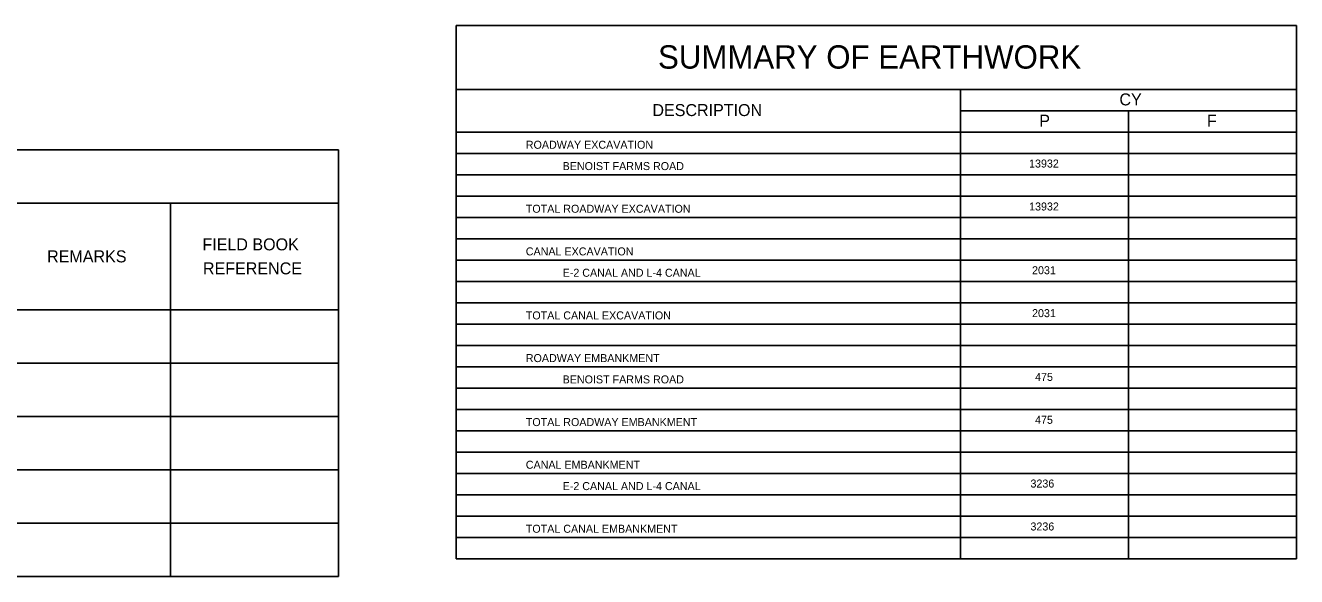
# Model space of a CAD drawing. Extents: x 0.1 to 38.9, y -11.7 to 25.8.
# Drawn here: x 29.62 to 38.87, y 21.71 to 25.72 of the extents above; entities that cross this region are included whole.
import ezdxf

# ---------------------------------------------------------------- set-up
doc = ezdxf.new("R2010")
doc.units = 0
doc.layers.add('Default', color=7, linetype='Continuous')

msp = doc.modelspace()

# ---------------------------------------------------------------- linework, layer by layer
at = {"layer": 'Default'}
for p, q in [((32.7527, 25.724), (32.7527, 21.8424)), ((32.7527, 25.724), (38.8663, 25.724)), ((38.8663, 25.724), (38.8663, 21.8424)), ((32.7527, 25.2582), (38.8663, 25.2582)), ((36.4209, 25.2582), (36.4209, 21.8424)), ((36.4209, 25.103), (38.8663, 25.103)), ((37.6436, 25.103), (37.6436, 21.8424)), ((32.7527, 24.9477), (38.8663, 24.9477)), ((17.4943, 24.8184), (31.8977, 24.8184)), ((31.8977, 24.8184), (31.8977, 21.7126)), ((32.7527, 24.7924), (38.8663, 24.7924)), ((32.7527, 24.6372), (38.8663, 24.6372)), ((17.4943, 24.4302), (31.8977, 24.4302)), ((30.6747, 24.4302), (30.6747, 21.7126)), ((32.7527, 24.4819), (38.8663, 24.4819)), ((32.7527, 24.3266), (38.8663, 24.3266)), ((32.7527, 24.1714), (38.8663, 24.1714)), ((32.7527, 24.0161), (38.8663, 24.0161)), ((32.7527, 23.8608), (38.8663, 23.8608)), ((32.7527, 23.7056), (38.8663, 23.7056)), ((17.4943, 23.6537), (31.8977, 23.6537)), ((32.7527, 23.5503), (38.8663, 23.5503)), ((32.7527, 23.395), (38.8663, 23.395)), ((17.4943, 23.2655), (31.8977, 23.2655)), ((32.7527, 23.2398), (38.8663, 23.2398)), ((32.7527, 23.0845), (38.8663, 23.0845)), ((17.4943, 22.8773), (31.8977, 22.8773)), ((32.7527, 22.9293), (38.8663, 22.9293)), ((32.7527, 22.774), (38.8663, 22.774)), ((32.7527, 22.6187), (38.8663, 22.6187)), ((17.4943, 22.489), (31.8977, 22.489)), ((32.7527, 22.4635), (38.8663, 22.4635)), ((32.7527, 22.3082), (38.8663, 22.3082)), ((17.4943, 22.1008), (31.8977, 22.1008)), ((32.7527, 22.1529), (38.8663, 22.1529)), ((32.7527, 21.9977), (38.8663, 21.9977)), ((32.7527, 21.8424), (38.8663, 21.8424)), ((17.4943, 21.7126), (31.8977, 21.7126))]:
    msp.add_line(p, q, dxfattribs=at)

# ---------------------------------------------------------------- texts
for s, height, p in [('SUMMARY OF EARTHWORK', 0.16983, (34.221, 25.4096)), ('DESCRIPTION', 0.087337, (34.1803, 25.0641)), ('CY', 0.08734, (37.5777, 25.1418)), ('P', 0.0873, (36.9945, 24.9865)), ('F', 0.0873, (38.2143, 24.9865)), ('ROADWAY EXCAVATION', 0.058225, (33.2594, 24.8264)), ('BENOIST FARMS ROAD', 0.058225, (33.5272, 24.6711)), ('13932', 0.05822, (36.9203, 24.6896)), ('TOTAL ROADWAY EXCAVATION', 0.058225, (33.2594, 24.3606)), ('13932', 0.05822, (36.9205, 24.3771)), ('FIELD BOOK', 0.08735, (30.9069, 24.0868)), ('REMARKS', 0.08735, (29.7771, 23.9994)), ('CANAL EXCAVATION', 0.058225, (33.2594, 24.0501)), ('REFERENCE', 0.08735, (30.9108, 23.9121)), ('E-2 CANAL AND L-4 CANAL', 0.058225, (33.5272, 23.8948)), ('2031', 0.05822, (36.942, 23.9132)), ('TOTAL CANAL EXCAVATION', 0.058225, (33.2594, 23.5843)), ('2031', 0.05822, (36.942, 23.6008)), ('ROADWAY EMBANKMENT', 0.058225, (33.2594, 23.2737)), ('BENOIST FARMS ROAD', 0.058225, (33.5272, 23.1185)), ('475', 0.05822, (36.9642, 23.1369)), ('TOTAL ROADWAY EMBANKMENT', 0.058225, (33.2594, 22.8079)), ('475', 0.05822, (36.964, 22.8244)), ('CANAL EMBANKMENT', 0.058225, (33.2594, 22.4974)), ('E-2 CANAL AND L-4 CANAL', 0.058225, (33.5272, 22.3421)), ('3236', 0.05822, (36.9305, 22.3606)), ('3236', 0.05822, (36.9303, 22.0481)), ('TOTAL CANAL EMBANKMENT', 0.058225, (33.2594, 22.0316))]:
    msp.add_text(s, height=height, dxfattribs=at).set_placement(p)

doc.saveas('drawing.dxf')
